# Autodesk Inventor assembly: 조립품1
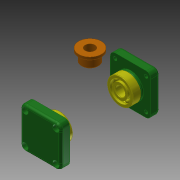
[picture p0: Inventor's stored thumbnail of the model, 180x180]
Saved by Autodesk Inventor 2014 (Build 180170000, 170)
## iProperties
Created: 2018-07
Part Number: 조립품1
Document SubType Name: Assembly
Designer: OA65
Author: OA65
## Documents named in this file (6)
- C:\Users\OA65\Desktop\480708V1001\조립품1.iam
- C:\Users\OA65\Desktop\480708V1001\본체.ipt
- C:\Users\OA65\Desktop\480708V1001\부시.ipt
- C:\Users\OA65\Desktop\480708V1001\뒤커버.ipt
- C:\Users\OA65\Desktop\480708V1001\앞커버.ipt
- C:\Users\OA65\Desktop\480708V1001\베어링 12x32x10.ipt
